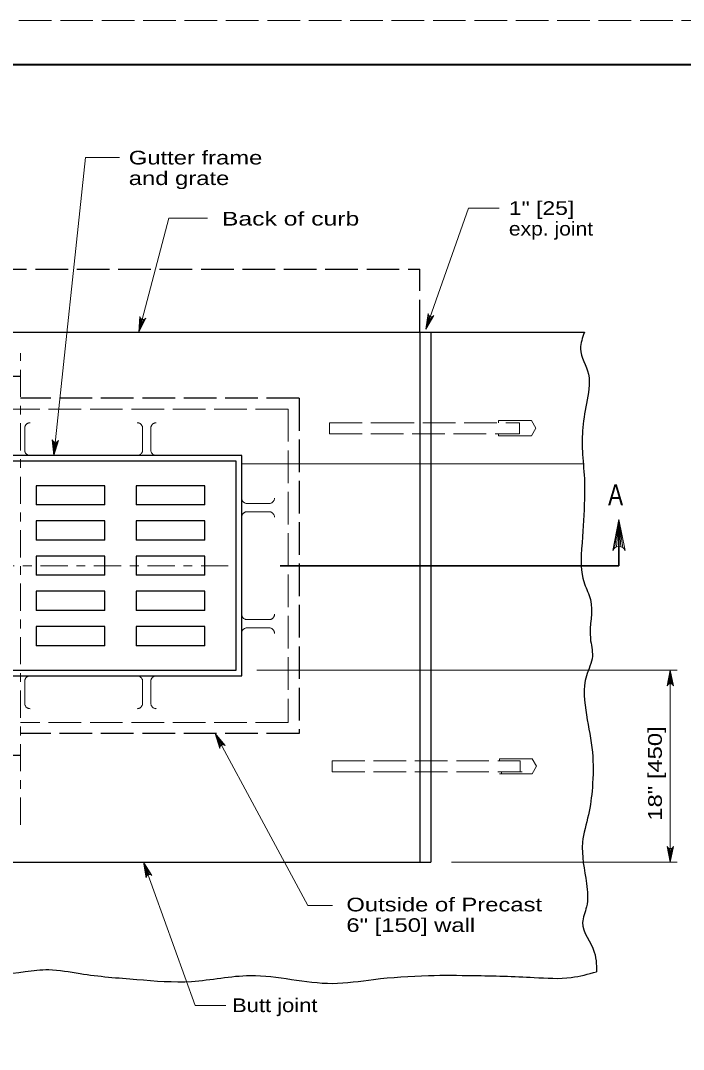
# Model space of a CAD drawing. Extents: x 1083.1 to 1117.1, y 719.4 to 763.4.
# Drawn here: x 1096.01 to 1103.56, y 751.62 to 763.35 of the extents above; entities that cross this region are included whole.
import ezdxf

# ---------------------------------------------------------------- set-up
doc = ezdxf.new("R2010")
doc.units = 0
doc.header["$LTSCALE"] = 0.062
doc.linetypes.add('DOT_DASHED', pattern=[7.7, 5, -1.2, 0.3, -1.2])
doc.linetypes.add('LONG_DASHED', pattern=[7.5, 6, -1.5])
doc.layers.add('1', color=7, linetype='Continuous', lineweight=13)

msp = doc.modelspace()

# ---------------------------------------------------------------- linework, layer by layer
at = {"layer": '1', "lineweight": 25}
for p, q in [((1085.12642, 762.85408), (1116.62642, 762.85408)), ((1089.198, 759.79842), (1102.43125, 759.79842)), ((1100.68133, 759.79842), (1100.68133, 753.75592)), ((1098.52517, 758.39233), (1095.56592, 758.39233)), ((1096.18433, 758.04875), (1096.18433, 757.83)), ((1097.3235, 758.04875), (1097.3235, 757.83)), ((1096.9655, 757.83), (1096.18433, 757.83)), ((1098.10475, 757.83), (1097.3235, 757.83)), ((1096.18433, 757.64733), (1096.18433, 757.42858)), ((1097.3235, 757.64733), (1097.3235, 757.42858)), ((1096.9655, 757.42858), (1096.18433, 757.42858)), ((1098.10475, 757.42858), (1097.3235, 757.42858)), ((1096.18433, 757.24583), (1096.18433, 757.02717)), ((1097.3235, 757.24583), (1097.3235, 757.02717)), ((1096.9655, 757.02717), (1096.18433, 757.02717)), ((1098.10475, 757.02717), (1097.3235, 757.02717)), ((1096.18433, 756.84442), (1096.18433, 756.62567)), ((1097.3235, 756.84442), (1097.3235, 756.62567)), ((1096.9655, 756.62567), (1096.18433, 756.62567)), ((1098.10475, 756.62567), (1097.3235, 756.62567)), ((1096.18433, 756.443), (1096.18433, 756.22425)), ((1097.3235, 756.443), (1097.3235, 756.22425)), ((1096.9655, 756.22425), (1096.18433, 756.22425)), ((1098.10475, 756.22425), (1097.3235, 756.22425)), ((1091.32908, 753.75592), (1100.68133, 753.75592))]:
    msp.add_line(p, q, dxfattribs=at)
at = {"layer": '1', "linetype": 'LONG_DASHED', "lineweight": 25}
for p, q in [((1091.45408, 760.517), (1100.55633, 760.517)), ((1100.55633, 759.79842), (1100.55633, 760.517)), ((1092.57908, 759.2985), (1096.00525, 759.2985)), ((1099.18142, 759.0485), (1096.00525, 759.0485)), ((1092.57908, 754.9745), (1096.00525, 754.9745))]:
    msp.add_line(p, q, dxfattribs=at)
at = {"layer": '1'}
for p, q in [((1097.3715, 759.95917), (1097.35242, 759.79842)), ((1097.38083, 759.95108), (1097.35242, 759.79842)), ((1097.41767, 759.94892), (1097.35242, 759.79842)), ((1100.65633, 759.99233), (1100.62442, 759.83358)), ((1100.665, 759.9835), (1100.62442, 759.83358)), ((1100.7015, 759.9785), (1100.62442, 759.83358)), ((1100.67517, 759.97825), (1100.62442, 759.83358)), ((1100.68967, 759.97608), (1100.62442, 759.83358)), ((1097.39142, 759.94658), (1097.35242, 759.79842)), ((1097.40608, 759.94567), (1097.35242, 759.79842)), ((1096.37825, 758.55408), (1096.38567, 758.39233)), ((1096.42542, 758.55158), (1096.38567, 758.39233)), ((1096.38875, 758.54758), (1096.38567, 758.39233)), ((1096.4145, 758.54642), (1096.38567, 758.39233)), ((1096.39992, 758.54492), (1096.38567, 758.39233)), ((1098.52517, 758.29858), (1102.419, 758.29858)), ((1102.77617, 757.338), (1102.82575, 757.66242)), ((1102.79692, 757.35025), (1102.82575, 757.66242)), ((1102.82575, 757.35592), (1102.82575, 757.66242)), ((1102.84842, 757.35258), (1102.82575, 757.66242)), ((1102.87058, 757.34175), (1102.82575, 757.66242)), ((1098.69967, 755.94317), (1103.48958, 755.94317)), ((1103.38617, 755.78092), (1103.41092, 755.94317)), ((1103.3965, 755.78708), (1103.41092, 755.94317)), ((1103.41092, 755.94317), (1103.41092, 753.75592)), ((1103.41092, 755.78992), (1103.41092, 755.94317)), ((1103.42225, 755.78825), (1103.41092, 755.94317)), ((1103.43333, 755.78283), (1103.41092, 755.94317)), ((1098.29475, 755.0895), (1098.22217, 755.22442)), ((1098.28342, 755.08017), (1098.22217, 755.22442)), ((1098.27717, 755.06983), (1098.22217, 755.22442)), ((1098.3055, 755.09333), (1098.22217, 755.22442)), ((1098.31783, 755.09383), (1098.22217, 755.22442)), ((1103.3885, 753.91617), (1103.41092, 753.75592)), ((1103.39958, 753.91075), (1103.41092, 753.75592)), ((1103.43575, 753.91808), (1103.41092, 753.75592)), ((1103.42533, 753.91192), (1103.41092, 753.75592)), ((1103.41092, 753.90908), (1103.41092, 753.75592)), ((1097.46092, 753.6125), (1097.40683, 753.75592)), ((1097.44842, 753.60483), (1097.40683, 753.75592)), ((1097.44083, 753.59542), (1097.40683, 753.75592)), ((1097.47208, 753.615), (1097.40683, 753.75592)), ((1097.48433, 753.61383), (1097.40683, 753.75592)), ((1100.91717, 753.75592), (1103.48958, 753.75592))]:
    msp.add_line(p, q, dxfattribs=at)
at = {"layer": '1', "linetype": 'DOT_DASHED'}
for p, q in [((1096.00525, 754.18167), (1096.00525, 759.56142)), ((1098.37175, 757.1365), (1093.6325, 757.1365))]:
    msp.add_line(p, q, dxfattribs=at)
at = {"layer": '1', "linetype": 'LONG_DASHED'}
for p, q in [((1099.05642, 758.9235), (1092.954, 758.9235)), ((1101.45458, 758.79075), (1101.45458, 758.76733)), ((1096.05217, 758.45483), (1096.05217, 758.70483)), ((1097.39583, 758.45483), (1097.39583, 758.70483)), ((1097.48958, 758.45483), (1097.48958, 758.70483)), ((1099.52517, 758.64233), (1099.52517, 758.76733)), ((1101.45458, 758.64233), (1101.45458, 758.61892)), ((1098.58767, 757.84558), (1098.83767, 757.84558)), ((1098.58767, 757.75183), (1098.83767, 757.75183)), ((1098.58767, 756.52108), (1098.83767, 756.52108)), ((1098.58767, 756.42733), (1098.83767, 756.42733)), ((1096.05217, 755.81808), (1096.05217, 755.56808)), ((1097.39583, 755.81808), (1097.39583, 755.56808)), ((1097.48958, 755.81808), (1097.48958, 755.56808)), ((1101.46325, 754.912), (1101.46325, 754.93542)), ((1101.48583, 754.76358), (1101.48583, 754.787))]:
    msp.add_line(p, q, dxfattribs=at)
at = {"layer": '1', "lineweight": 35}
for p, q in [((1102.82575, 757.1365), (1102.82575, 757.62075)), ((1102.12225, 757.1365), (1098.96417, 757.1365)), ((1102.12225, 757.1365), (1102.82575, 757.1365))]:
    msp.add_line(p, q, dxfattribs=at)
at = {"layer": '1', "linetype": 'LONG_DASHED'}
msp.add_lwpolyline([(1083.12642, 741.35408), (1117.12642, 741.35408), (1117.12642, 763.35408), (1083.12642, 763.35408)], close=True, dxfattribs=at)
at = {"layer": '1', "lineweight": 40}
msp.add_lwpolyline([(1085.12642, 762.85408), (1116.62642, 762.85408), (1116.62642, 741.85408), (1085.12642, 741.85408)], close=True, dxfattribs=at)
msp.add_lwpolyline([(1085.12642, 762.85408), (1116.62642, 762.85408), (1116.62642, 741.85408), (1085.12642, 741.85408)], close=True, dxfattribs=at)
at = {"layer": '1'}
for points in [[(1096.38567, 758.39233), (1096.74442, 761.79292), (1097.13158, 761.79292)], [(1100.62442, 759.83358), (1101.109, 761.21517), (1101.46092, 761.21517)], [(1097.35242, 759.79842), (1097.69475, 761.09967), (1098.13475, 761.09967)], [(1097.43175, 759.96067), (1097.35242, 759.79842), (1097.36325, 759.97867)], [(1100.71642, 759.989), (1100.62442, 759.83358), (1100.64958, 760.01242)], [(1101.45458, 758.79075), (1101.8295, 758.79075), (1101.87908, 758.70483), (1101.8295, 758.61892), (1101.45458, 758.61892)], [(1096.43742, 758.56533), (1096.38567, 758.39233), (1096.36683, 758.57192)], [(1102.75492, 757.30825), (1102.82575, 757.66242), (1102.89658, 757.30825)], [(1103.3755, 755.76608), (1103.41092, 755.94317), (1103.44633, 755.76608)], [(1098.22217, 755.22442), (1099.27867, 753.25942), (1099.56025, 753.25942)], [(1098.27483, 755.05167), (1098.22217, 755.22442), (1098.33717, 755.08525)], [(1101.46325, 754.76358), (1101.83817, 754.76358), (1101.88775, 754.8495), (1101.83817, 754.93542), (1101.46325, 754.93542)], [(1103.44633, 753.933), (1103.41092, 753.75592), (1103.3755, 753.933)], [(1097.40683, 753.75592), (1097.994, 752.1205), (1098.34592, 752.1205)], [(1097.43617, 753.57775), (1097.40683, 753.75592), (1097.50242, 753.60275)]]:
    msp.add_lwpolyline(points, dxfattribs=at)
at = {"layer": '1', "lineweight": 25}
for points in [[(1100.55633, 759.79842), (1100.55633, 756.61258), (1100.55633, 753.75592)], [(1093.54775, 758.32983), (1093.54775, 755.94317), (1098.46267, 755.94317), (1098.46267, 758.32983)], [(1098.46267, 758.32983), (1096.00333, 758.32983), (1093.54775, 758.32983)], [(1098.52517, 755.88067), (1098.52517, 756.67458), (1098.52517, 758.39233)], [(1096.9655, 757.83), (1096.9655, 758.04875), (1096.18433, 758.04875)], [(1098.10475, 757.83), (1098.10475, 758.04875), (1097.3235, 758.04875)], [(1096.9655, 757.42858), (1096.9655, 757.64733), (1096.18433, 757.64733)], [(1098.10475, 757.42858), (1098.10475, 757.64733), (1097.3235, 757.64733)], [(1096.9655, 757.02717), (1096.9655, 757.24583), (1096.18433, 757.24583)], [(1098.10475, 757.02717), (1098.10475, 757.24583), (1097.3235, 757.24583)], [(1096.9655, 756.62567), (1096.9655, 756.84442), (1096.18433, 756.84442)], [(1098.10475, 756.62567), (1098.10475, 756.84442), (1097.3235, 756.84442)], [(1096.9655, 756.22425), (1096.9655, 756.443), (1096.18433, 756.443)], [(1098.10475, 756.22425), (1098.10475, 756.443), (1097.3235, 756.443)], [(1093.48525, 755.88067), (1096.42658, 755.88067), (1098.52517, 755.88067)]]:
    msp.add_lwpolyline(points, dxfattribs=at)
at = {"layer": '1', "linetype": 'LONG_DASHED', "lineweight": 25}
msp.add_lwpolyline([(1099.18142, 759.0485), (1099.18142, 755.22442), (1096.00525, 755.22442)], dxfattribs=at)
at = {"layer": '1', "linetype": 'LONG_DASHED'}
for points in [[(1099.05642, 758.9235), (1099.05642, 755.34942), (1096.00525, 755.34942)], [(1099.52517, 758.64233), (1101.69158, 758.64233), (1101.69158, 758.76733)], [(1099.52517, 758.76733), (1100.11858, 758.76733), (1101.69158, 758.76733)], [(1099.55642, 754.912), (1099.55642, 754.787), (1101.72283, 754.787)], [(1099.55642, 754.912), (1101.70033, 754.912), (1101.70033, 754.787)]]:
    msp.add_lwpolyline(points, dxfattribs=at)
at = {"layer": '1'}
for centre, radius, start, end in [((1097.40107, 759.98348), 0.03822, 187.34759, 323.17371), ((1100.68773, 760.01422), 0.03822, 182.76121, 318.58733), ((1096.40343, 758.5829), 0.03822, 196.74996, 332.57608), ((1102.82582, 757.27963), 0.07644, 22.08782, 157.91395), ((1103.41096, 755.75177), 0.03822, 22.08782, 157.91395), ((1098.31282, 755.05588), 0.03822, 50.35343, 186.17956), ((1103.41088, 753.94727), 0.03822, 202.08782, 337.91395), ((1097.47438, 753.57685), 0.03822, 42.75514, 178.58127)]:
    msp.add_arc(centre, radius, start, end, dxfattribs=at)
at = {"layer": '1', "linetype": 'LONG_DASHED'}
for centre, major_axis, start_param, end_param in [((1096.11464, 758.70481), (-0.0625, 0), 4.71238898, 6.28318531), ((1097.33333, 758.70481), (0.0625, 0), 6.28318531, 7.85398163), ((1097.55207, 758.70481), (-0.0625, 0), 4.71238898, 6.28318531), ((1096.11464, 758.45485), (-0.0625, 0), 6.28318531, 7.85398163), ((1097.33333, 758.45485), (-0.0625, 0), 1.57079633, 3.14159265), ((1097.55207, 758.45485), (-0.0625, 0), 6.28318531, 7.85398163), ((1098.58769, 757.9081), (-0.0625, 0), 6.28318531, 7.85398163), ((1098.83767, 757.9081), (-0.0625, 0), 1.57079633, 3.14159265), ((1098.58769, 757.68938), (-0.0625, 0), 4.71238898, 6.28318531), ((1098.83767, 757.68938), (0.0625, 0), 6.28318531, 7.85398163), ((1098.58769, 756.58355), (-0.0625, 0), 6.28318531, 7.85398163), ((1098.83767, 756.58355), (0.0625, 0), 4.71238898, 6.28318531), ((1098.58769, 756.36483), (0.0625, 0), 1.57079633, 3.14159265), ((1098.83767, 756.36483), (0.0625, 0), 6.28318531, 7.85398163), ((1096.11464, 755.81808), (-0.0625, 0), 4.71238898, 6.28318531), ((1097.33333, 755.81808), (0.0625, 0), 6.28318531, 7.85398163), ((1097.55207, 755.81808), (-0.0625, 0), 4.71238898, 6.28318531), ((1096.11464, 755.56812), (-0.0625, 0), 6.28318531, 7.85398163), ((1097.33333, 755.56812), (-0.0625, 0), 1.57079633, 3.14159265), ((1097.55207, 755.56812), (-0.0625, 0), 6.28318531, 7.85398163)]:
    msp.add_ellipse(centre, major_axis=major_axis, ratio=0.999895, start_param=start_param, end_param=end_param, dxfattribs=at)
at = {"layer": '1', "lineweight": 25}
for points in [[(1102.43125, 759.79842), (1102.3885, 759.61167), (1102.47775, 759.32125), (1102.45542, 758.98608), (1102.41083, 758.67333), (1102.41083, 758.40525), (1102.43317, 758.0925), (1102.43317, 757.95842), (1102.41083, 757.46692), (1102.43317, 756.93067), (1102.50008, 756.75192), (1102.50008, 756.30508), (1102.52242, 756.104), (1102.45542, 755.88067), (1102.45542, 755.43383), (1102.52242, 755.00925), (1102.52242, 754.60708), (1102.47775, 754.29433), (1102.41083, 753.9815), (1102.45542, 753.51233), (1102.45542, 753.24433), (1102.41083, 753.06558), (1102.54467, 752.73042), (1102.567, 752.59642), (1102.571, 752.50608)], [(1090.46658, 752.50608), (1091.14975, 752.46233), (1091.953, 752.46233), (1092.26533, 752.46233), (1092.48842, 752.48467), (1092.80083, 752.507), (1092.97925, 752.507), (1093.31392, 752.41758), (1093.537, 752.44), (1094.42942, 752.37292), (1094.98717, 752.48467), (1095.478, 752.46233), (1096.05808, 752.507), (1096.32583, 752.52933), (1096.68267, 752.48467), (1097.32975, 752.41758), (1097.95442, 752.39525), (1098.62367, 752.46233), (1099.56075, 752.37292), (1100.02917, 752.41758), (1100.65392, 752.46233), (1101.16708, 752.46233), (1101.85867, 752.44), (1102.28258, 752.44), (1102.571, 752.50608)]]:
    msp.add_spline(points, degree=3, dxfattribs=at)

# ---------------------------------------------------------------- texts
at = {"layer": '1'}
for s, height, width, p in [('Gutter frame', 0.156, 1.3, (1097.23842, 761.71292)), ('and grate', 0.156, 1.3, (1097.23842, 761.47825)), ('1" [25]', 0.156, 1.25, (1101.57108, 761.13725)), ('Back of curb', 0.156, 1.35, (1098.30017, 761.01625)), ('exp. joint', 0.156, 1.15, (1101.57108, 760.90258)), ('A', 0.24, 0.8, (1102.70175, 757.82558)), ('Outside of Precast', 0.156, 1.3, (1099.71858, 753.19375)), ('6" [150] wall', 0.156, 1.3, (1099.71858, 752.95908)), ('Butt joint', 0.156, 1.2, (1098.4155, 752.04525))]:
    msp.add_text(s, height=height, dxfattribs=dict(at, width=width)).set_placement(p)
at = {"layer": '1', "width": 1.3}
msp.add_text('18" [450]', height=0.156, rotation=90, dxfattribs=at).set_placement((1103.31475, 754.22817))

doc.saveas('drawing.dxf')
